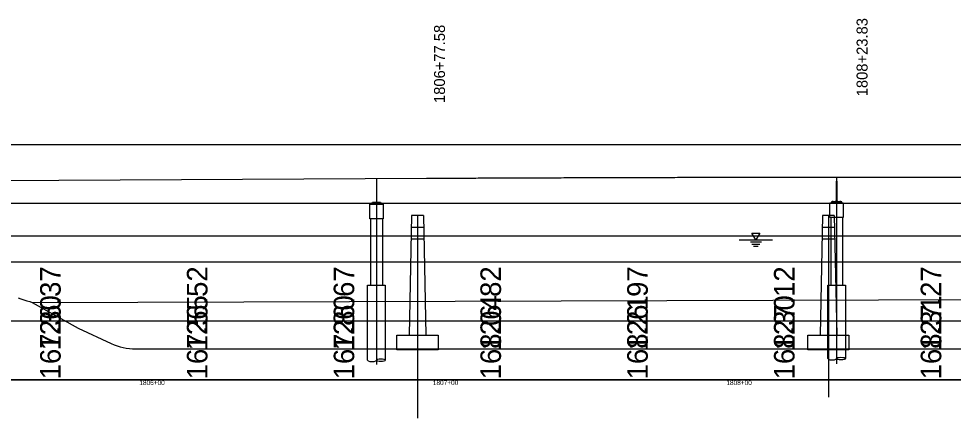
# Model space of a CAD drawing. Extents: x 2126510 to 2136144, y 865066 to 868066.
# Drawn here: x 2129003.4 to 2129321.8, y 866600.8 to 866736.8 of the extents above; entities that cross this region are included whole.
import ezdxf

# ---------------------------------------------------------------- set-up
doc = ezdxf.new("R2010")
doc.units = 0
for name, color, linetype in [('RD_DTM_BkLn1', 7, 'Continuous'), ('RD_EX_BldgApp', 7, 'Continuous'), ('RD_EX_Bridge', 7, 'Continuous'), ('RD_EX_GuardRail', 7, 'Continuous'), ('RD_EX_H2O', 7, 'Continuous'), ('RD_EX_Misc', 7, 'Continuous'), ('RD_EX_Misc_Golf_Fairway', 7, 'Continuous'), ('RD_HC_Data', 7, 'Continuous'), ('RD_HC_txCode', 7, 'Continuous')]:
    doc.layers.add(name, color=color, linetype=linetype)

msp = doc.modelspace()

# ---------------------------------------------------------------- linework, layer by layer
at = {"layer": 'RD_DTM_BkLn1'}
for p, q in [((2129127.05, 866674.01), (2129123.55, 866674.01)), ((2129123.55, 866674.01), (2129123.55, 866673.68)), ((2129126.63, 866674.3), (2129123.96, 866674.3)), ((2129123.96, 866674.01), (2129126.63, 866674.01)), ((2129127.05, 866673.68), (2129127.05, 866674.01)), ((2129280.3, 866674.48), (2129280.3, 866674.15)), ((2129281.71, 866674.48), (2129280.3, 866674.48)), ((2129280.71, 866674.48), (2129283.38, 866674.48)), ((2129283.8, 866674.48), (2129282.05, 866674.48)), ((2129283.8, 866674.15), (2129283.8, 866674.48)), ((2129123.3, 866668.68), (2129123.3, 866646.1)), ((2129127.3, 866668.68), (2129127.3, 866646.1)), ((2129280.05, 866669.15), (2129280.05, 866646.1)), ((2129284.05, 866669.15), (2129284.05, 866646.1))]:
    msp.add_line(p, q, dxfattribs=at)
for points in [[(2129123.05, 866673.68), (2129127.55, 866673.68), (2129127.55, 866668.68), (2129123.05, 866668.68)], [(2129279.8, 866674.15), (2129284.3, 866674.15), (2129284.3, 866669.15), (2129279.8, 866669.15)]]:
    msp.add_lwpolyline(points, close=True, dxfattribs=at)
for points in [[(2129122.3, 866620.57), (2129122.3, 866646.1), (2129128.3, 866646.1), (2129128.3, 866620.57)], [(2129279.05, 866621.11), (2129279.05, 866646.1), (2129285.05, 866646.1), (2129285.05, 866621.11)]]:
    msp.add_lwpolyline(points, dxfattribs=at)
for centre in [(2129123.8, 866620.57), (2129280.55, 866621.11)]:
    msp.add_ellipse(centre, major_axis=(-1.5, 0), ratio=0.310397, start_param=0, end_param=3.141593, dxfattribs=at)
for centre in [(2129126.8, 866620.57), (2129283.55, 866621.11)]:
    msp.add_ellipse(centre, major_axis=(-1.5, 0), ratio=0.310397, dxfattribs=at)
at = {"layer": 'RD_EX_BldgApp'}
for p, q in [((2129253.23, 866663.87), (2129255.85, 866663.87)), ((2129254.54, 866661.6), (2129253.23, 866663.87)), ((2129255.85, 866663.87), (2129254.54, 866661.6)), ((2129248.92, 866661.6), (2129260.17, 866661.6)), ((2129252.67, 866660.85), (2129256.42, 866660.85)), ((2129253.23, 866660.1), (2129255.85, 866660.1)), ((2129253.79, 866659.35), (2129255.29, 866659.35))]:
    msp.add_line(p, q, dxfattribs=at)
at = {"layer": 'RD_EX_Bridge'}
for p, q in [((2129123.96, 866674.3), (2129123.96, 866674.01)), ((2129126.63, 866674.01), (2129126.63, 866674.3)), ((2129280.71, 866674.78), (2129280.71, 866674.48)), ((2129281.71, 866674.78), (2129281.71, 866674.48)), ((2129282.38, 866674.48), (2129282.38, 866674.78)), ((2129283.38, 866674.48), (2129283.38, 866674.78))]:
    msp.add_line(p, q, dxfattribs=at)
at = {"layer": 'RD_EX_GuardRail'}
for p, q in [((2131097.7, 866693.9), (2126517.45, 866693.9)), ((2131097.7, 866673.9), (2129000.13, 866673.9)), ((2131097.7, 866653.9), (2126517.45, 866653.9)), ((2131097.7, 866633.9), (2126517.45, 866633.9)), ((2131097.7, 866613.9), (2126517.45, 866613.9))]:
    msp.add_line(p, q, dxfattribs=at)
at = {"layer": 'RD_EX_H2O'}
msp.add_line((2129043.31, 866624.4), (2129361.63, 866624.4), dxfattribs=at)
for points in [[(2129003.19, 866641.8), (2129004.19, 866641.48), (2129005.19, 866641.15), (2129006.19, 866640.83), (2129007.19, 866640.51), (2129008.03, 866640.24)], [(2129008.03, 866640.24), (2129023.67, 866631.45), (2129034.93, 866626.25)]]:
    msp.add_lwpolyline(points, dxfattribs=at)
msp.add_arc((2129043.31, 866644.4), 20, 245.2113, 270, dxfattribs=at)
at = {"layer": 'RD_EX_Misc'}
for p, q in [((2127961.73, 866676.62), (2129142.37, 866682.52)), ((2129139.28, 866669.78), (2129139.28, 866600.79)), ((2129279.28, 866669.78), (2129279.28, 866607.94)), ((2127368.72, 866613.9), (2131522.97, 866613.9))]:
    msp.add_line(p, q, dxfattribs=at)
for points in [[(2127275.85, 866613.9), (2127275.85, 866662.9), (2131989.68, 866662.9)], [(2129008.05, 866640.24), (2129404.47, 866641.43)]]:
    msp.add_lwpolyline(points, dxfattribs=at)
msp.add_spline([(2129142.37, 866682.52), (2129149.42, 866682.56), (2129156.47, 866682.59), (2129163.52, 866682.62), (2129170.57, 866682.65), (2129177.62, 866682.68), (2129184.67, 866682.7), (2129191.72, 866682.73), (2129198.77, 866682.75), (2129205.82, 866682.77), (2129212.87, 866682.79), (2129219.92, 866682.81), (2129226.97, 866682.83), (2129234.02, 866682.85), (2129241.07, 866682.86), (2129248.12, 866682.87), (2129255.17, 866682.88), (2129262.23, 866682.89), (2129269.28, 866682.9), (2129276.33, 866682.9), (2129283.38, 866682.91), (2129290.43, 866682.91), (2129297.48, 866682.91), (2129304.53, 866682.91), (2129311.58, 866682.91), (2129318.63, 866682.9), (2129325.68, 866682.9), (2129332.73, 866682.89), (2129339.78, 866682.88), (2129346.83, 866682.87), (2129353.88, 866682.86), (2129360.93, 866682.85), (2129367.98, 866682.83), (2129375.03, 866682.82), (2129382.08, 866682.8), (2129389.13, 866682.78), (2129396.18, 866682.76), (2129403.23, 866682.74), (2129410.28, 866682.71), (2129417.33, 866682.68), (2129424.38, 866682.66), (2129431.43, 866682.63), (2129438.48, 866682.6), (2129445.53, 866682.56), (2129452.58, 866682.53), (2129459.63, 866682.49), (2129466.68, 866682.46), (2129473.73, 866682.42), (2129480.78, 866682.38), (2129487.83, 866682.34), (2129494.88, 866682.29)], degree=3, dxfattribs=at)
at = {"layer": 'RD_EX_Misc_Golf_Fairway'}
for p, q in [((2129137.28, 866669.78), (2129136.44, 866629.1)), ((2129141.28, 866669.78), (2129137.28, 866669.78)), ((2129141.28, 866669.78), (2129142.13, 866629.1)), ((2129277.28, 866669.78), (2129276.44, 866629.1)), ((2129281.28, 866669.78), (2129277.28, 866669.78)), ((2129281.28, 866669.78), (2129282.13, 866629.1)), ((2129141.37, 866665.78), (2129137.21, 866665.78)), ((2129281.37, 866665.78), (2129277.21, 866665.78)), ((2129141.45, 866661.78), (2129137.12, 866661.78)), ((2129281.45, 866661.78), (2129277.12, 866661.78))]:
    msp.add_line(p, q, dxfattribs=at)
for points in [[(2129132.28, 866629.1), (2129146.28, 866629.1), (2129146.28, 866624.1), (2129132.28, 866624.1)], [(2129272.28, 866629.1), (2129286.28, 866629.1), (2129286.28, 866624.1), (2129272.28, 866624.1)]]:
    msp.add_lwpolyline(points, close=True, dxfattribs=at)
at = {"layer": 'RD_HC_Data'}
for p, q in [((2129282.05, 866682.91), (2129282.05, 866619.34)), ((2129125.3, 866682.44), (2129125.3, 866619.14))]:
    msp.add_line(p, q, dxfattribs=at)
at = {"layer": 'RD_HC_txCode'}
for p, q in [((2129281.96, 866681.48), (2129281.96, 866674.78)), ((2129282.13, 866681.48), (2129282.13, 866674.78))]:
    msp.add_line(p, q, dxfattribs=at)

# ---------------------------------------------------------------- texts
at = {"layer": 'RD_EX_Misc'}
for s, height, p in [('1808+23.83', 3.75, (2129292.61, 866710.43)), ('1806+77.58', 3.75, (2129148.65, 866708.14)), ('126.37', 7, (2129017.72, 866623.9)), ('126.52', 7, (2129067.72, 866623.9)), ('126.67', 7, (2129117.72, 866623.9)), ('126.82', 7, (2129167.72, 866623.9)), ('126.97', 7, (2129217.72, 866623.9)), ('127.12', 7, (2129267.72, 866623.9)), ('127.27', 7, (2129317.72, 866623.9)), ('167.30', 7, (2129017.72, 866614.05)), ('167.55', 7, (2129067.72, 866614.05)), ('167.80', 7, (2129117.72, 866614.05)), ('168.04', 7, (2129167.72, 866614.05)), ('168.21', 7, (2129217.72, 866614.05)), ('168.30', 7, (2129267.72, 866614.05)), ('168.31', 7, (2129317.72, 866614.05))]:
    msp.add_text(s, height=height, rotation=90, dxfattribs=at).set_placement(p)
for s, p in [('1806+00', (2129044.51, 866612.1)), ('1807+00', (2129144.51, 866612.1)), ('1808+00', (2129244.51, 866612.1))]:
    msp.add_text(s, height=1.6, dxfattribs=at).set_placement(p)

doc.saveas('drawing.dxf')
